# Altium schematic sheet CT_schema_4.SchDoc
size 255 x 159 mm
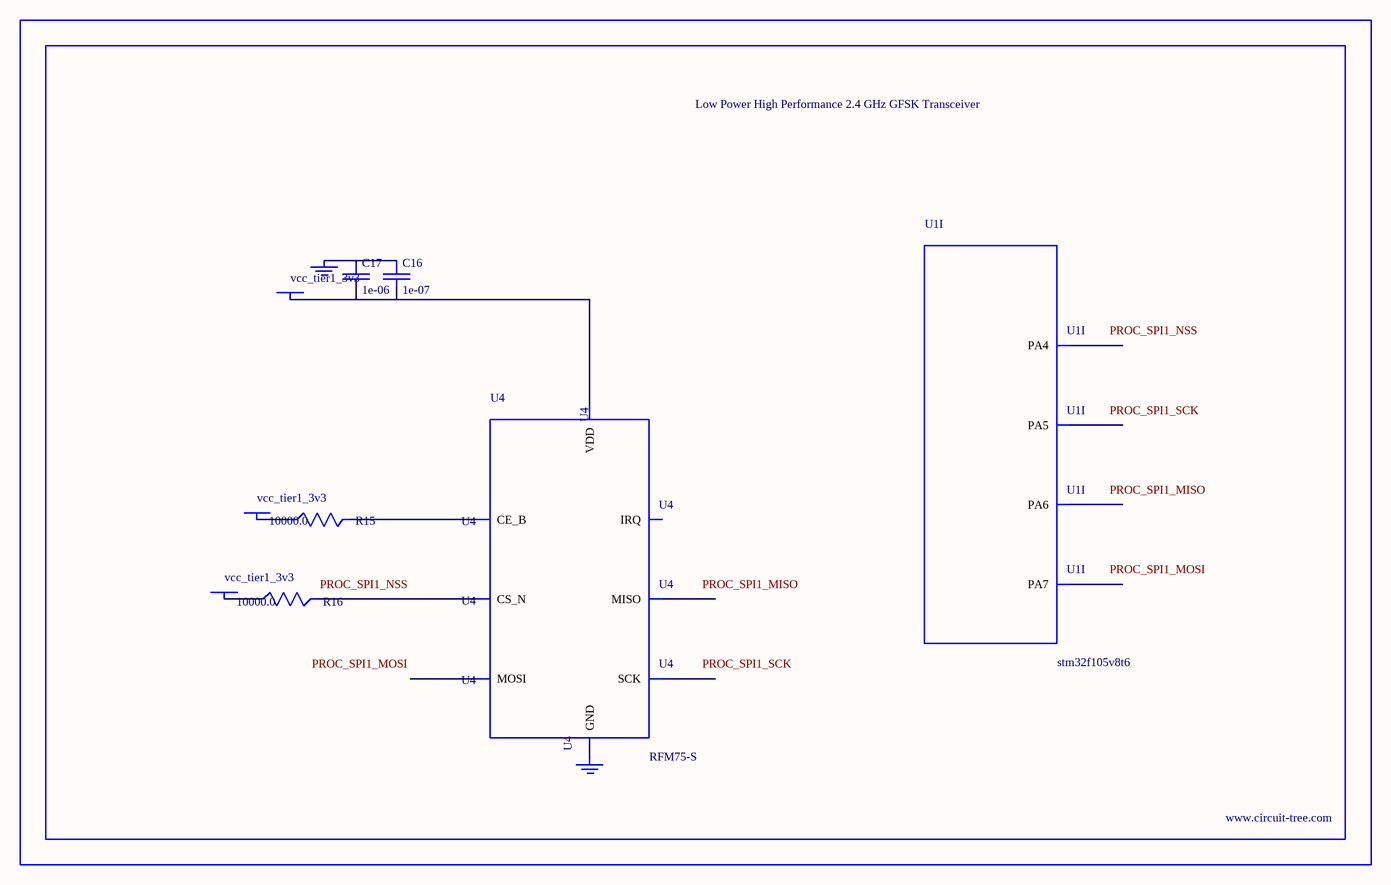
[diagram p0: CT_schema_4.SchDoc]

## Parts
BORDER3  (no value)
C16  1e-07  [C0402]
C17  1e-06  [C0603]
GND_INSTANCE_3_0  (no value)
GND_INSTANCE_3_1  (no value)
POWER_INSTANCE_3_0  vcc_tier1_3v3
POWER_INSTANCE_3_1  vcc_tier1_3v3
POWER_INSTANCE_3_2  vcc_tier1_3v3
R15  10000.0  [R0603]
R16  10000.0  [R0603]
U1  stm32f105v8t6  [LQFP100]  (part I of 10)
U4  RFM75-S  [RFM75-S]

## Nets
NetC16_1: C16.1 C17.1 GND_INSTANCE_3_0.0(GND)
NetC16_2: C16.2 C17.2 POWER_INSTANCE_3_0.0(PWR) U4.2(VDD)
NetGND_INSTANCE_3_1_0: GND_INSTANCE_3_1.0(GND) U4.1(GND)
NetPOWER_INSTANCE_3_1_0: POWER_INSTANCE_3_1.0(PWR) R15.1
NetPOWER_INSTANCE_3_2_0: POWER_INSTANCE_3_2.0(PWR) R16.1
NetR15_2: R15.2 U4.3(CE_B)
NetR16_2: R16.2 U4.4(CS_N)

Not connected (* = marked no-connect by the designer): U1 29(PA4) 30(PA5) 31(PA6) 32(PA7); U4 5(SCK) 6(MOSI) 7(MISO) 8(IRQ)

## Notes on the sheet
- Labels drawn without touching a wire or pin: PROC_SPI1_MISO, PROC_SPI1_MOSI, PROC_SPI1_NSS, PROC_SPI1_SCK

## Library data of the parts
BORDER3 = BORDER_PAGE3
C16 = C0402C104K3RACTU
C17 = C0603C105K3RACTU
GND_INSTANCE_3_0 GND_INSTANCE_3_1 = GND
POWER_INSTANCE_3_0-POWER_INSTANCE_3_2 = PWR
R15 R16 = RC0603JR-0710KL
